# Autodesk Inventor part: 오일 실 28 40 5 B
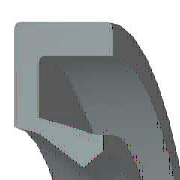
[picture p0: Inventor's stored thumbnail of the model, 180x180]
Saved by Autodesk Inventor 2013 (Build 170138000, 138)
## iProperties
IsCustomPart: 1
Created: 2012-02
Part Number: 오일 실 28 40 5 B
Material: 고무
Description: 오일 실 - 비스프링, 조립 GA
Document SubType Name: Modeling
Standard: JIS B 2402
Designer: mduedu
Standards Organization: JIS
Language: ko-KR
Size Designation: 28 40 5 B
Categories: <MemberInstance><Categories><Category DisplayName="샤프트 부품" InternalName="7f7aeb1f-a693-4053-b835-cee3144e0d98" Mnemonic="SHFT"><Category DisplayName="실링" Intern
Density: 0.93 g/cm^3
Author: mduedu
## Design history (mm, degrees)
body "Solid1"
revolve "회전1" stored, may be unused: angle "d27" = 360 deg
fillet "모깎기1" dims "d28" = 0.25 (= 0.05 x b)
sketch "스케치2"
  geometry: L1 (15.971, -3.75)-(16.571, -5); L2 (15.171, -3.438)-(15.971, -3.75); L3 (14, -1.375)-(15.171, -3.438); L4 (14.923, -0.75)-(14, -1.375); L5 (17.6, -4.375)-(14.923, -0.75); L6 (17.6, -0.25)-(17.6, -4.375); L7 (18.8, -0.25)-(17.6, -0.25); L8 (18.8, 0)-(18.8, -0.25); L9 (20, 0)-(18.8, 0); L10 (20, -5)-(20, 0); L11 (16.571, -5)-(20, -5); L12 (0, -9.6)-(0, 1.6) reference; L13 (28, 0)-(14, 0) reference
  constraints: 22 end point, 3 horizontal, 3 vertical
  dimensions: "d2" = 5 distance of L10.start L9.start (= b); "d4" = 1.2 distance of L9.start L8.start (= 0.1 x dd - 0.1 x Diam); "d6" = 0.25 distance of L8.start L7.start (= 0.05 x b); "d8" = 0.92308 horizontal distance of L4.start L3.start (= 0.0769231 x dd - 0.0769231 x Diam); "d10" = 0.625 vertical distance of L5.start L10.start (= 0.125 x b); "d12" = 1.2 distance of L7.start L6.start (= 0.1 x dd - 0.1 x Diam); "d14" = 0.5 vertical distance of L4.start L6.start (= 0.1 x b); "d16" = 3.42857 distance of L1.end L10.start (= 0.285714 x dd - 0.285714 x Diam); "d18" = 0.6 horizontal distance of L1.start L1.end (= 0.05 x dd - 0.05 x Diam); "d20" = 0.625 vertical distance of L4.start L3.start (= 0.125 x b); "d22" = 1.25 vertical distance of L1.start L1.end (= 0.25 x b); "d24" = 0.8 horizontal distance of L2.start L1.start (= 0.0666667 x dd - 0.0666667 x Diam); "d26" = 0.3125 vertical distance of L2.start L1.start (= 0.0625 x b); "d29" = 0 distance between parallel lines of L13 L9; "d30" = 14 distance from line of L3.start L12 (= 0.5 x Diam); "d31" = 20 distance between parallel lines of L12 L10 (= 0.5 x dd)
other parameters: "Diam" = 28 [user parameter; used in 7 equation terms], "b" = 5 [user parameter; used in 8 equation terms], "d1" = 8 (derived), "d3" = 2 (derived), "d5" = 0.4 (derived), "d7" = 1.53846 (derived), "d9" = 1 (derived), "d11" = 2 (derived), "d13" = 0.8 (derived), "d15" = 5.71429 (derived), "d17" = 1 (derived), "d19" = 1 (derived), "d21" = 2 (derived), "d23" = 1.33333 (derived), "d25" = 0.5 (derived), "d32" = 0
